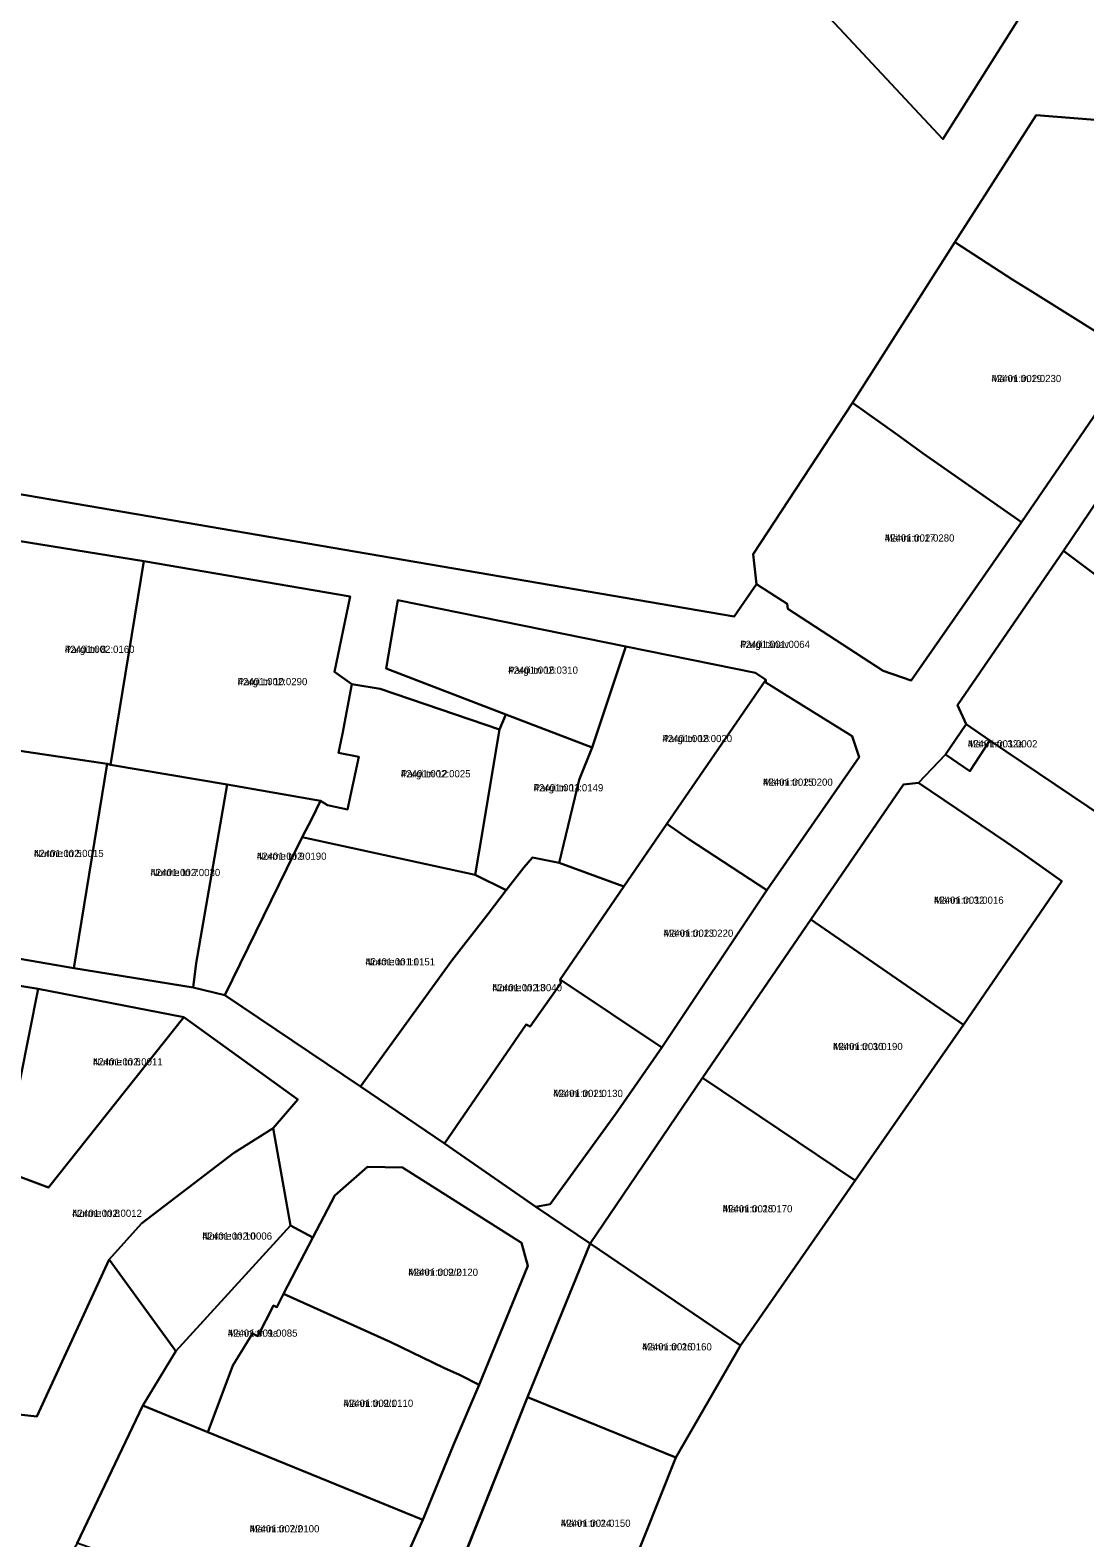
# Model space of a CAD drawing. Extents: x 595979 to 597983, y 6604231 to 6607350.
# Drawn here: x 596804.9 to 597024.3, y 6605736 to 6606049.7 of the extents above; entities that cross this region are included whole.
import ezdxf

# ---------------------------------------------------------------- set-up
doc = ezdxf.new("R2010")
doc.units = 0
for name, color, linetype in [('L_AADRESS', 7, 'Continuous'), ('PIIR', 7, 'Continuous'), ('TUNNUS', 7, 'Continuous')]:
    doc.layers.add(name, color=color, linetype=linetype)

msp = doc.modelspace()

# ---------------------------------------------------------------- linework, layer by layer
at = {"layer": 'PIIR'}
for points in [[(597083.05, 6606050.71), (597087.59, 6606045.02), (597057.4, 6606015.57), (597045.35, 6606028.13), (597042.19, 6606029.76), (597014.23, 6606031.96), (596997.32, 6606005.56), (596975.98, 6605972.14), (596955.37, 6605940.6), (596956.04, 6605934.38), (596951.35, 6605927.69), (596664.52, 6605976.79), (596695.91, 6606173.63)], [(597030.56, 6606083.77), (596994.79, 6606027), (596935.06, 6606090.99)], [(596935.06, 6606090.99), (596994.79, 6606027), (597030.56, 6606083.77)], [(597065.74, 6606009.24), (597019.89, 6605941.36), (596997.87, 6605909.24), (596999.66, 6605905.3), (596995.37, 6605898.95), (596989.77, 6605893.07), (596986.59, 6605892.7), (596967.32, 6605864.66), (596944.83, 6605831.72), (596921.4, 6605797.22), (596910.13, 6605804.85), (596913.12, 6605805.38), (596926.72, 6605824.11), (596936.33, 6605837.99), (596958.18, 6605870.74), (596977.38, 6605898.4), (596975.95, 6605902.79), (596961.29, 6605911.87), (596957.97, 6605913.93), (596957.96, 6605914.48), (596955.82, 6605915.96), (596928.84, 6605921.4), (596881.41, 6605931.09), (596878.95, 6605916.85), (596903.9, 6605907.3), (596902.55, 6605904.15), (596877.71, 6605912.64), (596871.85, 6605913.62), (596868.2, 6605916.17), (596871.51, 6605931.82), (596828.54, 6605939.21), (596802.41, 6605943.38)], [(596664.52, 6605976.79), (596951.35, 6605927.69), (596956.04, 6605934.38), (596962.38, 6605930.28), (596962.55, 6605929.29), (596982.37, 6605916.35), (596988.21, 6605914.36), (597011.15, 6605947.31), (597034.82, 6605981.8)], [(597072.09, 6605693.55), (597015.38, 6605695.99), (597015.83, 6605704.95), (596922.84, 6605711.45), (596939.26, 6605752.73), (596952.71, 6605775.97), (596976.59, 6605810.34), (596999.07, 6605842.72), (597019.57, 6605872.58), (597011.42, 6605878.38), (597008.14, 6605880.65), (596989.77, 6605893.07), (596995.37, 6605898.95), (597000.43, 6605895.48), (597004.6, 6605901.84), (597028.34, 6605885.84)], [(596880.63, 6605726.43), (596886.61, 6605739.74), (596893.02, 6605755.31), (596898.3, 6605767.83), (596908.48, 6605792.56), (596907.11, 6605797.35), (596882.35, 6605813.02), (596875.13, 6605813.17), (596868.3, 6605807.18), (596863.71, 6605798.49), (596859.1, 6605800.95), (596855.44, 6605821.22), (596860.57, 6605827.16), (596836.88, 6605844.3), (596806.56, 6605850.22), (596777.97, 6605854.86), (596766.12, 6605856.78), (596737.27, 6605861.65), (596707.41, 6605866.94), (596700.7, 6605827.04), (596695.89, 6605797.54), (596692.66, 6605778.16), (596685.03, 6605734.09)], [(596793.49, 6605858.05), (596814.02, 6605854.49), (596838.85, 6605850.48), (596845.41, 6605848.88), (596873.67, 6605829.92), (596891.14, 6605818.01), (596910.13, 6605804.85), (596921.4, 6605797.22), (596908.36, 6605765.26), (596891.49, 6605722.66)]]:
    msp.add_lwpolyline(points, dxfattribs=at)
for points in [[(597032.68, 6605931.79), (597019.89, 6605941.36), (597065.74, 6606009.24), (597089.62, 6606038.98), (597111.34, 6605994), (597134.57, 6605996), (597100.21, 6605954.46), (597074.28, 6605966.24), (597069.54, 6605924.99), (597056.42, 6605921), (597052.59, 6605923.77), (597051.39, 6605922.09), (597037.84, 6605931.7), (597037.49, 6605931.33), (597034.59, 6605933.31)], [(597034.82, 6605981.8), (597013, 6605995.46), (597009.37, 6605997.72), (596997.32, 6606005.56), (597014.23, 6606031.96), (597042.19, 6606029.76), (597045.35, 6606028.13), (597057.4, 6606015.57), (597035.59, 6605983.48)], [(596975.98, 6605972.14), (596997.32, 6606005.56), (597009.37, 6605997.72), (597013, 6605995.46), (597034.82, 6605981.8), (597011.15, 6605947.31), (596990.71, 6605961.58), (596985.38, 6605965.43)], [(596962.55, 6605929.29), (596962.38, 6605930.28), (596956.04, 6605934.38), (596955.37, 6605940.6), (596975.98, 6605972.14), (596985.38, 6605965.43), (596990.71, 6605961.58), (597011.15, 6605947.31), (596988.21, 6605914.36), (596982.37, 6605916.35)], [(596802.41, 6605943.38), (596828.54, 6605939.21), (596821.66, 6605896.78), (596820.96, 6605897.03), (596795.71, 6605900.79)], [(597019.89, 6605941.36), (597032.68, 6605931.79), (597034.59, 6605933.31), (597037.49, 6605931.33), (597037.84, 6605931.7), (597051.39, 6605922.09), (597052.59, 6605923.77), (597056.42, 6605921), (597054.7, 6605908.63), (597042.72, 6605888.08), (597031.31, 6605885.03), (597028.34, 6605885.84), (597004.6, 6605901.84), (596999.66, 6605905.3), (596997.87, 6605909.24)], [(596828.54, 6605939.21), (596871.51, 6605931.82), (596868.2, 6605916.17), (596871.85, 6605913.62), (596869.92, 6605903.27), (596869.09, 6605899.33), (596873.27, 6605898.44), (596870.95, 6605887.52), (596866.81, 6605888.4), (596865.3, 6605889.3), (596845.89, 6605892.74), (596821.66, 6605896.78)], [(596928.84, 6605921.4), (596921.83, 6605900.43), (596903.9, 6605907.3), (596878.95, 6605916.85), (596881.41, 6605931.09)], [(596928.84, 6605921.4), (596955.82, 6605915.96), (596957.96, 6605914.48), (596937.39, 6605884.54), (596928.45, 6605871.52), (596914.97, 6605876.4), (596919.15, 6605893.66), (596921.83, 6605900.43)], [(596871.85, 6605913.62), (596877.71, 6605912.64), (596902.55, 6605904.15), (596898.33, 6605878.83), (596897.5, 6605873.89), (596861.54, 6605881.74), (596863.49, 6605885.58), (596865.3, 6605889.3), (596866.81, 6605888.4), (596870.95, 6605887.52), (596873.27, 6605898.44), (596869.09, 6605899.33), (596869.92, 6605903.27)], [(596957.96, 6605914.48), (596957.97, 6605913.93), (596961.29, 6605911.87), (596975.95, 6605902.79), (596977.38, 6605898.4), (596958.18, 6605870.74), (596941.92, 6605881.32), (596937.39, 6605884.54)], [(596902.55, 6605904.15), (596903.9, 6605907.3), (596921.83, 6605900.43), (596919.15, 6605893.66), (596914.97, 6605876.4), (596909.45, 6605877.54), (596907.63, 6605875.44), (596903.92, 6605870.76), (596897.5, 6605873.89), (596898.33, 6605878.83)], [(596995.37, 6605898.95), (596999.66, 6605905.3), (597004.6, 6605901.84), (597000.43, 6605895.48)], [(596790.43, 6605901.62), (596795.71, 6605900.79), (596820.96, 6605897.03), (596814.02, 6605854.49), (596793.49, 6605858.05), (596790.9, 6605896.71), (596790.77, 6605898.05)], [(596839.46, 6605855.53), (596838.85, 6605850.48), (596814.02, 6605854.49), (596820.96, 6605897.03), (596821.66, 6605896.78), (596845.89, 6605892.74)], [(596845.89, 6605892.74), (596865.3, 6605889.3), (596863.49, 6605885.58), (596861.54, 6605881.74), (596845.41, 6605848.88), (596838.85, 6605850.48), (596839.46, 6605855.53)], [(596989.77, 6605893.07), (597008.14, 6605880.65), (597011.42, 6605878.38), (597019.57, 6605872.58), (596999.07, 6605842.72), (596967.32, 6605864.66), (596986.59, 6605892.7)], [(596937.39, 6605884.54), (596941.92, 6605881.32), (596958.18, 6605870.74), (596936.33, 6605837.99), (596915.21, 6605852.16), (596928.45, 6605871.52)], [(596845.41, 6605848.88), (596861.54, 6605881.74), (596897.5, 6605873.89), (596903.92, 6605870.76), (596900.22, 6605865.84), (596892.67, 6605856.08), (596873.67, 6605829.92)], [(596907.63, 6605875.44), (596909.45, 6605877.54), (596914.97, 6605876.4), (596928.45, 6605871.52), (596915.21, 6605852.16), (596915.29, 6605851.37), (596908.92, 6605842.37), (596908.14, 6605842.75), (596891.14, 6605818.01), (596873.67, 6605829.92), (596892.67, 6605856.08), (596900.22, 6605865.84), (596903.92, 6605870.76)], [(596967.32, 6605864.66), (596999.07, 6605842.72), (596976.59, 6605810.34), (596944.83, 6605831.72)], [(596777.97, 6605854.86), (596806.56, 6605850.22), (596799.08, 6605812.46), (596797.08, 6605800.79), (596785.86, 6605802.44), (596772.76, 6605804.36)], [(596806.56, 6605850.22), (596836.88, 6605844.3), (596808.71, 6605808.89), (596799.08, 6605812.46)], [(596891.14, 6605818.01), (596908.14, 6605842.75), (596908.92, 6605842.37), (596915.29, 6605851.37), (596915.21, 6605852.16), (596936.33, 6605837.99), (596926.72, 6605824.11), (596913.12, 6605805.38), (596910.13, 6605804.85)], [(596836.88, 6605844.3), (596860.57, 6605827.16), (596855.44, 6605821.22), (596847.24, 6605815.99), (596828.1, 6605801.37), (596821.32, 6605793.9), (596806.3, 6605761.22), (596781.4, 6605764.04), (596785.86, 6605802.44), (596797.08, 6605800.79), (596799.08, 6605812.46), (596808.71, 6605808.89)], [(596944.83, 6605831.72), (596976.59, 6605810.34), (596952.71, 6605775.97), (596921.4, 6605797.22)], [(596855.44, 6605821.22), (596859.1, 6605800.95), (596835.19, 6605774.82), (596821.32, 6605793.9), (596828.1, 6605801.37), (596847.24, 6605815.99)], [(596857.6, 6605786.74), (596863.71, 6605798.49), (596868.3, 6605807.18), (596875.13, 6605813.17), (596882.35, 6605813.02), (596907.11, 6605797.35), (596908.48, 6605792.56), (596898.3, 6605767.83), (596894.25, 6605769.87), (596890.99, 6605771.37), (596879.95, 6605776.72)], [(596841.88, 6605757.97), (596828.35, 6605763.51), (596835.19, 6605774.82), (596859.1, 6605800.95), (596863.71, 6605798.49), (596857.6, 6605786.74), (596856.22, 6605784), (596855.54, 6605784.34), (596852.3, 6605777.91), (596851.14, 6605778.5), (596847.1, 6605771.84)], [(596921.4, 6605797.22), (596952.71, 6605775.97), (596939.26, 6605752.73), (596908.36, 6605765.26)], [(596783.16, 6605636.35), (596742.46, 6605643.65), (596743.26, 6605663.24), (596743.76, 6605681.63), (596750.48, 6605716.38), (596683.77, 6605728.06), (596685.03, 6605734.09), (596751.3, 6605722.5), (596753.04, 6605730.24), (596756.61, 6605766.92), (596781.4, 6605764.04), (596806.3, 6605761.22), (596821.32, 6605793.9), (596835.19, 6605774.82), (596828.35, 6605763.51), (596814.68, 6605734.88), (596800.26, 6605709.74), (596788.69, 6605683.33), (596797.85, 6605679.12), (596789.61, 6605661.31), (596786.57, 6605654.73), (596789.87, 6605651.91)], [(596841.88, 6605757.97), (596847.1, 6605771.84), (596851.14, 6605778.5), (596852.3, 6605777.91), (596855.54, 6605784.34), (596856.22, 6605784), (596857.6, 6605786.74), (596879.95, 6605776.72), (596890.99, 6605771.37), (596894.25, 6605769.87), (596898.3, 6605767.83), (596893.02, 6605755.31), (596886.61, 6605739.74)], [(596908.36, 6605765.26), (596939.26, 6605752.73), (596922.84, 6605711.45), (596891.4, 6605722.68)], [(596828.35, 6605763.51), (596841.88, 6605757.97), (596886.61, 6605739.74), (596880.63, 6605726.43), (596873.49, 6605710.72), (596867.83, 6605713.3), (596856.93, 6605718.44), (596845.7, 6605723.18), (596841.09, 6605725.22), (596831.87, 6605728.75), (596814.68, 6605734.88)]]:
    msp.add_lwpolyline(points, close=True, dxfattribs=at)

# ---------------------------------------------------------------- texts
at = {"layer": 'L_AADRESS'}
for s, p in [('Männi tn 19', (597004.93, 6605976.43)), ('Männi tn 17', (596982.71, 6605943.25)), ('Pargi tn 8', (596812.12, 6605920.09)), ('Pargi tänav', (596952.65, 6605921.12)), ('Pargi tn 16', (596904.38, 6605915.76)), ('Pargi tn 10', (596848.08, 6605913.37)), ('Pargi tn 18', (596936.46, 6605901.53)), ('Männi tn 32a', (596999.98, 6605900.43)), ('Pargi tn 12', (596882.04, 6605894.21)), ('Männi tn 15', (596957.39, 6605892.45)), ('Pargi tn 14', (596909.66, 6605891.29)), ('Nurme tn 5', (596805.7, 6605877.62)), ('Nurme tn 9', (596852.07, 6605877.05)), ('Nurme tn 7', (596829.96, 6605873.66)), ('Männi tn 32', (596992.95, 6605867.9)), ('Männi tn 13', (596936.7, 6605861.03)), ('Nurme tn 11', (596874.66, 6605855.08)), ('Nurme tn 13', (596901.06, 6605849.7)), ('Männi tn 30', (596971.95, 6605837.46)), ('Nurme tn 6', (596817.98, 6605834.27)), ('Männi tn 11', (596913.73, 6605827.7)), ('Nurme tn 8', (596813.67, 6605802.76)), ('Männi tn 28', (596949, 6605803.7)), ('Nurme tn 10', (596840.74, 6605798.02)), ('Männi tn 9/2', (596883.59, 6605790.5)), ('Männi tn 9a', (596846.03, 6605777.83)), ('Männi tn 26', (596932.23, 6605774.98)), ('Männi tn 9/1', (596870.11, 6605763.24)), ('Männi tn 24', (596915.33, 6605738.28)), ('Männi tn 7/2', (596850.59, 6605737.12))]:
    msp.add_text(s, height=1.5, dxfattribs=at).set_placement(p)
at = {"layer": 'TUNNUS'}
for s, p in [('42401:002:0230', (597004.93, 6605976.43)), ('42401:002:0280', (596982.71, 6605943.25)), ('42401:002:0160', (596812.12, 6605920.09)), ('42401:001:0064', (596952.65, 6605921.12)), ('42401:002:0310', (596904.38, 6605915.76)), ('42401:002:0290', (596848.08, 6605913.37)), ('42401:002:0020', (596936.46, 6605901.53)), ('42401:001:0002', (596999.98, 6605900.43)), ('42401:002:0025', (596882.04, 6605894.21)), ('42401:002:0200', (596957.39, 6605892.45)), ('42401:001:0149', (596909.66, 6605891.29)), ('42401:002:0015', (596805.7, 6605877.62)), ('42401:002:0190', (596852.07, 6605877.05)), ('42401:002:0030', (596829.96, 6605873.66)), ('42401:001:0016', (596992.95, 6605867.9)), ('42401:002:0220', (596936.7, 6605861.03)), ('42401:001:0151', (596874.66, 6605855.08)), ('42401:002:0040', (596901.06, 6605849.7)), ('42401:001:0190', (596971.95, 6605837.46)), ('42401:002:0011', (596817.98, 6605834.27)), ('42401:002:0130', (596913.73, 6605827.7)), ('42401:002:0012', (596813.67, 6605802.76)), ('42401:001:0170', (596949, 6605803.7)), ('42401:002:0006', (596840.74, 6605798.02)), ('42401:002:0120', (596883.59, 6605790.5)), ('42401:001:0085', (596846.03, 6605777.83)), ('42401:001:0160', (596932.23, 6605774.98)), ('42401:002:0110', (596870.11, 6605763.24)), ('42401:001:0150', (596915.33, 6605738.28)), ('42401:002:0100', (596850.59, 6605737.12))]:
    msp.add_text(s, height=1.5, dxfattribs=at).set_placement(p)

doc.saveas('drawing.dxf')
